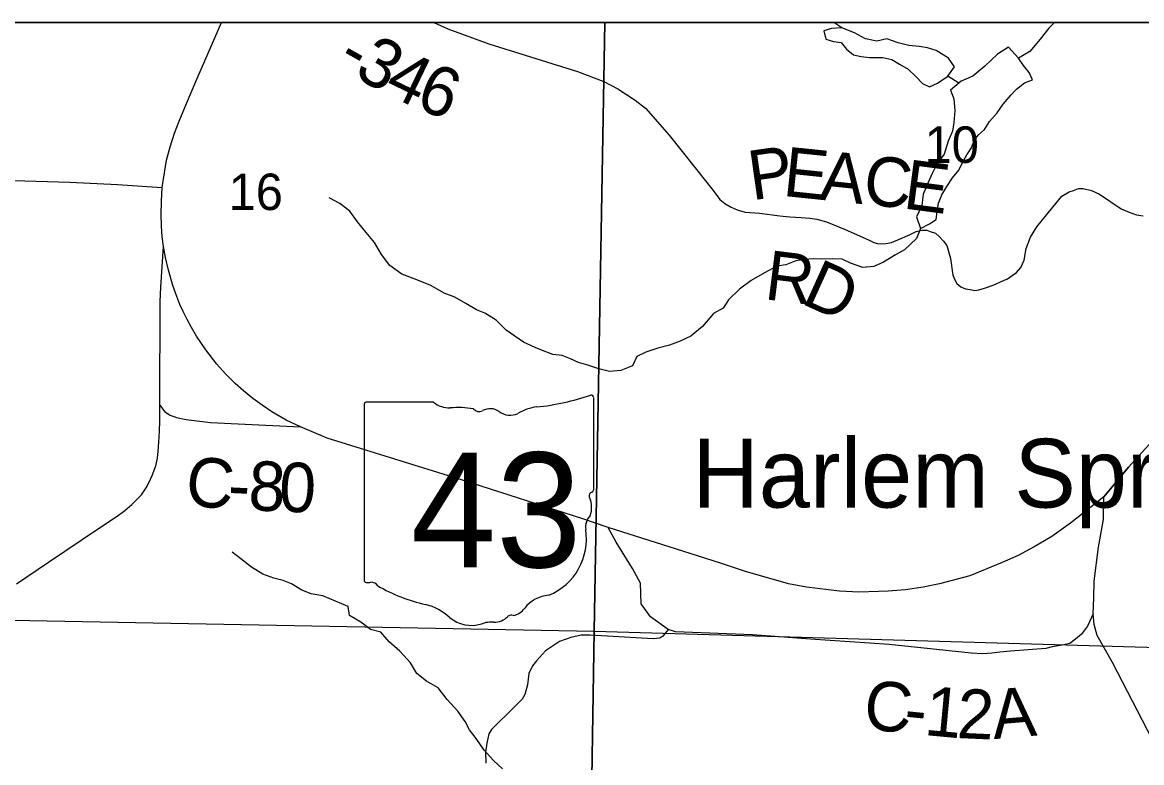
# Model space of a CAD drawing. Extents: x -3.6 to 34, y 0 to 32.8.
# Drawn here: x -2.413 to -1.128, y 31.993 to 32.843 of the extents above; entities that cross this region are included whole.
import ezdxf

# ---------------------------------------------------------------- set-up
doc = ezdxf.new("R2010")
doc.units = 0
for name, color, linetype in [('GM_X_Corporation', 7, 'Continuous'), ('GM_X_County_Road', 7, 'Continuous'), ('GM_X_County_Road_Text', 7, 'Continuous'), ('GM_X_Minor_Lake', 7, 'Continuous'), ('GM_X_Minor_River', 7, 'Continuous'), ('GM_X_Section_Text', 7, 'Continuous'), ('GM_X_State_Location', 7, 'Continuous'), ('GM_X_State_Route', 7, 'Continuous'), ('GM_X_State_Shield', 7, 'Continuous'), ('GM_X_Township_Road', 7, 'Continuous'), ('GM_X_Township_Road_Text', 7, 'Continuous'), ('GM_X_Unincorporated_Text', 7, 'Continuous'), ('SH_Data', 7, 'Continuous')]:
    doc.layers.add(name, color=color, linetype=linetype)

msp = doc.modelspace()

# ---------------------------------------------------------------- linework, layer by layer
at = {"layer": 'GM_X_Corporation'}
for points in [[(3.1705, 28.9337), (3.1705, 32.8429), (-3.6295, 32.8429), (-3.6295, 26.0429), (2.3706, 26.0429), (2.3712, 26.0804), (2.3716, 26.1248), (2.3732, 26.2253), (2.3789, 26.6097), (2.3911, 27.5117), (2.3952, 27.9336), (2.3997, 28.282), (2.4082, 28.9473), (2.5416, 28.945), (2.5837, 28.9442), (2.8343, 28.9397)], [(3.1705, 30.458), (3.1705, 32.8429), (-3.6295, 32.8429), (-3.6295, 30.6462), (-3.5736, 30.6453), (-2.8007, 30.6338), (-2.7027, 30.634), (-2.3541, 30.6318), (-0.5034, 30.5954), (-0.453, 30.5952), (-0.398, 30.5946), (0.2583, 30.5905), (0.2578, 30.5133), (0.3556, 30.5115), (0.4055, 30.5105), (1.2437, 30.4948), (1.7819, 30.4857), (3.0419, 30.4594)], [(-1.7439, 32.8429), (-2.7551, 32.8429), (-2.7692, 32.1629), (-1.7561, 32.1438)], [(-0.7278, 32.8429), (-1.7439, 32.8429), (-1.7561, 32.1438), (-0.7385, 32.1141)], [(-2.7692, 32.1629), (-1.7561, 32.1438), (-1.7722, 31.1326), (-2.786, 31.1483)], [(-1.7561, 32.1438), (-0.7385, 32.1141), (-0.7569, 31.1125), (-1.7722, 31.1326)]]:
    msp.add_lwpolyline(points, close=True, dxfattribs=at)
at = {"layer": 'GM_X_County_Road'}
msp.add_line((-1.1709, 32.298), (-1.1593, 32.3119), dxfattribs=at)
for points in [[(-2.4353, 32.6616), (-2.3583, 32.6594), (-2.3035, 32.6568), (-2.2523, 32.6534)], [(-1.1593, 32.3119), (-1.1425, 32.3319), (-1.0919, 32.388), (-1.0547, 32.4298), (-1.0295, 32.4572)], [(-2.2549, 32.4034), (-2.2489, 32.3954), (-2.2431, 32.3919), (-2.2358, 32.389), (-2.2246, 32.3867), (-2.1966, 32.3833), (-2.0933, 32.3782)], [(-1.1094, 32.0076), (-1.1609, 32.1076), (-1.1787, 32.1385), (-1.1819, 32.1513), (-1.1831, 32.1635), (-1.1825, 32.1816), (-1.1819, 32.2012), (-1.177, 32.2402), (-1.1714, 32.2719), (-1.1713, 32.2845), (-1.1709, 32.298)], [(-1.1831, 32.1635), (-1.1898, 32.1494), (-1.1966, 32.1401), (-1.2036, 32.1343), (-1.2101, 32.1296), (-1.2188, 32.1277), (-1.2302, 32.1258), (-1.2376, 32.1239), (-1.2782, 32.1207), (-1.2904, 32.1194), (-1.2995, 32.1182), (-1.3097, 32.1178), (-1.3234, 32.1183), (-1.4174, 32.1285), (-1.5076, 32.1346), (-1.5742, 32.1394), (-1.6628, 32.1429), (-1.6712, 32.1454), (-1.6915, 32.16), (-1.7023, 32.175), (-1.703, 32.1988), (-1.7122, 32.2155), (-1.7307, 32.246), (-1.74, 32.2629)]]:
    msp.add_lwpolyline(points, dxfattribs=at)
at = {"layer": 'GM_X_Minor_Lake'}
for points in [[(-1.4717, 32.8367), (-1.4838, 32.8357), (-1.4925, 32.833), (-1.4901, 32.8235), (-1.4814, 32.821), (-1.4727, 32.8199), (-1.4665, 32.812), (-1.4585, 32.8057), (-1.4497, 32.8035), (-1.4399, 32.8025), (-1.4248, 32.8027), (-1.4145, 32.8001), (-1.4054, 32.7949), (-1.3955, 32.7893), (-1.387, 32.7807), (-1.379, 32.7728), (-1.371, 32.7688), (-1.362, 32.773), (-1.3501, 32.7809)], [(-1.3501, 32.7809), (-1.3424, 32.7919), (-1.3494, 32.8016), (-1.3635, 32.8105), (-1.3734, 32.8138), (-1.3828, 32.8152), (-1.395, 32.8162), (-1.4071, 32.8194), (-1.42, 32.8238), (-1.4314, 32.8214), (-1.4446, 32.8238), (-1.4572, 32.8309), (-1.4717, 32.8367)], [(-1.2689, 32.8018), (-1.2803, 32.8144), (-1.2931, 32.8062), (-1.3076, 32.7927), (-1.3214, 32.7812), (-1.3346, 32.7753), (-1.3469, 32.7649), (-1.343, 32.7551), (-1.342, 32.7418), (-1.3433, 32.7278), (-1.3447, 32.7179), (-1.3495, 32.7064), (-1.3542, 32.6916), (-1.3627, 32.6801), (-1.3678, 32.6702), (-1.373, 32.6583), (-1.3785, 32.6457), (-1.3801, 32.6324), (-1.386, 32.6195), (-1.3813, 32.6063)], [(-1.3813, 32.6063), (-1.371, 32.6114), (-1.3635, 32.6164), (-1.3624, 32.6251), (-1.3607, 32.6354), (-1.357, 32.6449), (-1.3511, 32.6545), (-1.3447, 32.6644), (-1.3373, 32.6732), (-1.3336, 32.6812), (-1.3284, 32.6908), (-1.3228, 32.6988), (-1.3199, 32.7075), (-1.3147, 32.7137), (-1.308, 32.7198), (-1.3024, 32.729), (-1.2934, 32.7389), (-1.2867, 32.7489), (-1.2774, 32.7596), (-1.2711, 32.7661), (-1.2621, 32.7734), (-1.253, 32.777), (-1.2565, 32.7853), (-1.2631, 32.7935), (-1.2689, 32.8018)]]:
    msp.add_lwpolyline(points, dxfattribs=at)
at = {"layer": 'GM_X_Minor_River'}
for points in [[(-1.2277, 32.8429), (-1.2341, 32.8362), (-1.2441, 32.8236), (-1.256, 32.8094), (-1.2689, 32.8018), (-1.2803, 32.8144), (-1.2931, 32.8062), (-1.3076, 32.7927), (-1.3214, 32.7812), (-1.3346, 32.7753), (-1.3469, 32.7649), (-1.343, 32.7551), (-1.342, 32.7418), (-1.3433, 32.7278), (-1.3447, 32.7179), (-1.3495, 32.7064), (-1.3542, 32.6916), (-1.3627, 32.6801), (-1.3678, 32.6702), (-1.373, 32.6583), (-1.3785, 32.6457), (-1.3801, 32.6324), (-1.386, 32.6195), (-1.3813, 32.6063), (-1.386, 32.5948), (-1.3998, 32.5817), (-1.4103, 32.5759), (-1.4238, 32.5674), (-1.4351, 32.5623), (-1.4476, 32.5614), (-1.462, 32.5665), (-1.4715, 32.5709), (-1.4821, 32.5711), (-1.4946, 32.5709), (-1.5045, 32.5712), (-1.5147, 32.5707), (-1.5245, 32.569), (-1.5361, 32.5643), (-1.5463, 32.563), (-1.5606, 32.5552), (-1.576, 32.5463), (-1.5894, 32.5366), (-1.6018, 32.5243), (-1.608, 32.5147), (-1.6193, 32.5085), (-1.6319, 32.4936), (-1.645, 32.4824), (-1.6574, 32.4769), (-1.6698, 32.4722), (-1.683, 32.4686), (-1.697, 32.4642), (-1.7071, 32.4591), (-1.7122, 32.4484), (-1.7254, 32.443), (-1.7386, 32.442), (-1.7508, 32.4449)], [(-1.3373, 32.773), (-1.3501, 32.7809), (-1.3424, 32.7919), (-1.3494, 32.8016), (-1.3635, 32.8105), (-1.3734, 32.8138), (-1.3828, 32.8152), (-1.395, 32.8162), (-1.4071, 32.8194), (-1.42, 32.8238), (-1.4314, 32.8214), (-1.4446, 32.8238), (-1.4572, 32.8309), (-1.4717, 32.8367), (-1.4809, 32.8429)], [(-1.7508, 32.4449), (-1.7633, 32.4493), (-1.774, 32.4521), (-1.7835, 32.4566), (-1.793, 32.4602), (-1.8036, 32.4616), (-1.8135, 32.4652), (-1.8238, 32.4693), (-1.8371, 32.4755), (-1.8474, 32.4826), (-1.8573, 32.4893), (-1.8685, 32.5009), (-1.8815, 32.5087), (-1.8914, 32.5127), (-1.9036, 32.5201), (-1.9162, 32.5271), (-1.9283, 32.5319), (-1.9436, 32.5408), (-1.9577, 32.5463), (-1.9676, 32.5503), (-1.9771, 32.5536), (-1.9909, 32.5636), (-2.0005, 32.5764), (-2.0083, 32.59), (-2.0179, 32.6016), (-2.0279, 32.6136), (-2.0368, 32.626), (-2.0483, 32.6349), (-2.0605, 32.6412)], [(-1.8613, 31.9856), (-1.8716, 31.9953), (-1.8824, 32.0069), (-1.8917, 32.0204), (-1.8994, 32.0302), (-1.9044, 32.04), (-1.9125, 32.0516), (-1.9249, 32.0651), (-1.9353, 32.0786), (-1.9486, 32.0864), (-1.9597, 32.095), (-1.9671, 32.1074), (-1.9794, 32.1205), (-1.9917, 32.1313), (-2.0009, 32.1426), (-2.013, 32.1454), (-2.0241, 32.154), (-2.0371, 32.1618), (-2.0384, 32.172), (-2.0677, 32.1841), (-2.081, 32.1866), (-2.0916, 32.1906), (-2.1035, 32.198), (-2.1134, 32.2017), (-2.124, 32.2046), (-2.1366, 32.2093), (-2.1495, 32.2171), (-2.1618, 32.2268), (-2.1717, 32.2342)]]:
    msp.add_lwpolyline(points, dxfattribs=at)
at = {"layer": 'GM_X_State_Route'}
msp.add_line((-1.1593, 32.3119), (-1.1709, 32.298), dxfattribs=at)
for points in [[(-2.2523, 32.6534), (-2.2496, 32.6699), (-2.247, 32.6847), (-2.2431, 32.7001), (-2.2381, 32.7155), (-2.2325, 32.7293), (-2.2243, 32.7495), (-2.2135, 32.7749), (-2.1994, 32.8076), (-2.1842, 32.8429)], [(-2.2508, 32.5855), (-2.2522, 32.5967), (-2.2528, 32.6091), (-2.2533, 32.6217), (-2.2531, 32.6374), (-2.2523, 32.6534)], [(-2.4194, 32.1979), (-2.3828, 32.2229), (-2.3254, 32.2614), (-2.3038, 32.2759), (-2.295, 32.2823), (-2.2869, 32.289), (-2.2759, 32.3004), (-2.2707, 32.3084), (-2.267, 32.3149), (-2.2635, 32.3224), (-2.2594, 32.3335), (-2.2576, 32.3425), (-2.2569, 32.3502), (-2.2561, 32.3607), (-2.2553, 32.3729), (-2.2549, 32.3857), (-2.2549, 32.4034), (-2.2543, 32.5221), (-2.2536, 32.5388), (-2.2508, 32.5855)], [(-1.1709, 32.298), (-1.2094, 32.2676), (-1.2307, 32.2525), (-1.2391, 32.2474), (-1.251, 32.2407), (-1.2695, 32.2307), (-1.2877, 32.2227), (-1.3247, 32.2073), (-1.3597, 32.1981), (-1.3785, 32.1943), (-1.3985, 32.1913), (-1.4187, 32.1896), (-1.4297, 32.1891), (-1.4521, 32.1885), (-1.4746, 32.1897), (-1.5122, 32.1941), (-1.533, 32.1982), (-1.5823, 32.2123), (-1.611, 32.2217), (-1.6616, 32.2379), (-1.74, 32.2629), (-1.769, 32.2725), (-1.9075, 32.3169), (-2.0628, 32.3655), (-2.0933, 32.3782), (-2.1097, 32.3861), (-2.1262, 32.3957), (-2.1374, 32.4031), (-2.1479, 32.4107), (-2.1588, 32.4195), (-2.1683, 32.4281), (-2.1794, 32.4393), (-2.1894, 32.4505), (-2.2021, 32.4668), (-2.2127, 32.4825), (-2.2186, 32.4925), (-2.2235, 32.5016), (-2.2282, 32.5109), (-2.2317, 32.519), (-2.2365, 32.531), (-2.2399, 32.5407), (-2.245, 32.5583), (-2.2485, 32.5727), (-2.2508, 32.5855)], [(-1.0295, 32.4572), (-1.0547, 32.4298), (-1.0919, 32.388), (-1.1425, 32.3319), (-1.1593, 32.3119)]]:
    msp.add_lwpolyline(points, dxfattribs=at)
at = {"layer": 'GM_X_State_Shield'}
for p, q in [((-1.7567, 32.3068), (-1.7567, 32.4114)), ((-2.0203, 32.403), (-2.0203, 32.2029)), ((-1.9405, 32.4065), (-2.0178, 32.4065)), ((-1.7567, 32.3068), (-1.7567, 32.3068))]:
    msp.add_line(p, q, dxfattribs=at)
for centre, radius, start, end in [((-1.8506, 32.6793), 0.2796, 275.8445, 288.9065), ((-1.7596, 32.4119), 0.00294, 351.8621, 97.738), ((-2.0173, 32.4035), 0.00305, 98.1301, 188.1301), ((-1.9221, 32.4297), 0.0296, 231.6195, 271.1119), ((-1.9123, 32.2941), 0.1064, 80.4867, 94.9883), ((-1.8882, 32.4045), 0.00855, 219.7921, 297.1024), ((-1.8756, 32.3814), 0.0178, 54.4667, 119.1411), ((-1.8149, 32.3454), 0.0563, 97.3462, 120.7689), ((-1.8527, 32.4131), 0.0214, 233.8562, 294.8282), ((-1.7598, 32.3064), 0.00314, 289.6038, 7.7341), ((-1.7574, 32.2991), 0.00454, 107.944, 210.337), ((-1.7863, 32.2858), 0.0273, 340.033, 23.6496), ((-1.7462, 32.263), 0.0198, 136.8065, 186.9296), ((-1.8349, 32.2496), 0.0699, 292.3089, 8.9858), ((-2.0173, 32.2025), 0.00308, 171.9584, 258.3066), ((-2.0168, 32.223), 0.0235, 267.339, 280.6039), ((-2.012, 32.1914), 0.00848, 29.7484, 93.2717), ((-1.905, 32.3712), 0.2019, 240.4129, 257.1985), ((-1.8055, 32.1467), 0.0383, 94.4031, 142.5768), ((-1.9652, 32.113), 0.0632, 47.1842, 75.836), ((-1.854, 32.1835), 0.0226, 282.8732, 323.2771), ((-1.8968, 32.1904), 0.0401, 230.7004, 286.2918), ((-1.8737, 32.1212), 0.0329, 85.6951, 111.2099), ((-1.8707, 32.1754), 0.0214, 268.777, 315.5493), ((-1.8514, 32.156), 0.00601, 65.7517, 132.6484)]:
    msp.add_arc(centre, radius, start, end, dxfattribs=at)
at = {"layer": 'GM_X_Township_Road'}
for points in [[(-1.9401, 32.8429), (-1.9242, 32.8353), (-1.8771, 32.8184), (-1.7754, 32.7866), (-1.7451, 32.7749), (-1.7288, 32.7665), (-1.7091, 32.7536), (-1.6972, 32.7444), (-1.6701, 32.7133), (-1.6269, 32.6591), (-1.6184, 32.6483), (-1.6118, 32.6393), (-1.6061, 32.6347), (-1.5988, 32.6306), (-1.592, 32.6274), (-1.5829, 32.6248), (-1.5664, 32.6236), (-1.5431, 32.6208), (-1.5315, 32.6196), (-1.5185, 32.6187), (-1.5087, 32.618), (-1.5006, 32.6167), (-1.4895, 32.6136), (-1.4681, 32.6051), (-1.4412, 32.5931), (-1.4352, 32.5902), (-1.4308, 32.5888), (-1.4267, 32.5885), (-1.4212, 32.589), (-1.4149, 32.59), (-1.4047, 32.5944), (-1.3932, 32.5992), (-1.3865, 32.6027), (-1.3799, 32.6043), (-1.3741, 32.6041), (-1.3702, 32.6027), (-1.3643, 32.6008), (-1.36, 32.5968), (-1.3549, 32.5917), (-1.3513, 32.5866), (-1.3469, 32.5716), (-1.3445, 32.5525), (-1.3421, 32.5473), (-1.3396, 32.5429), (-1.3352, 32.539), (-1.3298, 32.537), (-1.3243, 32.5359), (-1.3192, 32.535), (-1.3146, 32.5357), (-1.3081, 32.5376), (-1.2982, 32.5411), (-1.2863, 32.5465), (-1.2816, 32.5485), (-1.2761, 32.552), (-1.2712, 32.5554), (-1.2664, 32.5612), (-1.2623, 32.5699), (-1.2603, 32.5831), (-1.255, 32.5963), (-1.2477, 32.608), (-1.2415, 32.6162), (-1.2193, 32.6434), (-1.2109, 32.6482), (-1.2057, 32.6499), (-1.2002, 32.6519), (-1.1947, 32.6522), (-1.1851, 32.6498), (-1.1759, 32.6454), (-1.1511, 32.6289), (-1.1419, 32.6247), (-1.1336, 32.622), (-1.1259, 32.6206)], [(-1.6712, 32.1454), (-1.6772, 32.1378), (-1.6809, 32.1358), (-1.6885, 32.1349), (-1.7606, 32.1391), (-1.771, 32.1392), (-1.7828, 32.1364), (-1.796, 32.1317), (-1.8119, 32.1209), (-1.8224, 32.1097), (-1.8271, 32.1037), (-1.8313, 32.0952), (-1.8327, 32.0822), (-1.8359, 32.0711), (-1.8389, 32.0654), (-1.8472, 32.057), (-1.8739, 32.0306), (-1.8772, 32.0258), (-1.8794, 32.0152), (-1.8808, 32.0045), (-1.8806, 31.992)]]:
    msp.add_lwpolyline(points, dxfattribs=at)
at = {"layer": 'SH_Data'}
msp.add_line((-3.6295, 32.8429), (3.1705, 32.8429), dxfattribs=at)

# ---------------------------------------------------------------- texts
at = {"layer": 'GM_X_County_Road_Text'}
for s, rotation, p in [('C', 354.6137, (-2.2268, 32.2884)), ('8', 357.5964, (-2.1539, 32.2827)), ('0', 357.7127, (-2.1188, 32.2812)), ('-', 357.3117, (-2.1775, 32.2838)), ('C', 354.2156, (-1.4483, 32.0316)), ('1', 354.6332, (-1.3782, 32.0245)), ('2', 357.3947, (-1.3404, 32.021)), ('A', 4.8796, (-1.2973, 32.0196)), ('-', 354.295, (-1.4018, 32.0269))]:
    msp.add_text(s, height=0.0568, rotation=rotation, dxfattribs=at).set_placement(p)
at = {"layer": 'GM_X_Section_Text'}
for s, p in [('10', (-1.3767, 32.6815)), ('16', (-2.1758, 32.6273))]:
    msp.add_text(s, height=0.04186, rotation=0, dxfattribs=at).set_placement(p)
at = {"layer": 'GM_X_State_Location'}
for s in ['s', 'r']:
    msp.add_text(s, height=0.000189, dxfattribs=at).set_placement((-1.8915, 32.2897))
msp.add_text('43', height=0.000189, rotation=0, dxfattribs=at).set_placement((-1.9392, 32.2759))
at = {"layer": 'GM_X_State_Shield'}
msp.add_text('43', height=0.13184, dxfattribs=at).set_placement((-1.9667, 32.217))
at = {"layer": 'GM_X_Township_Road_Text'}
for s, rotation, p in [('3', 330.5036, (-2.0334, 32.7816)), ('-', 330.5383, (-2.0537, 32.7931)), ('4', 334.2842, (-1.9993, 32.7625)), ('6', 338.8826, (-1.9632, 32.7453)), ('P', 8.0733, (-1.5749, 32.6384)), ('E', 354.0881, (-1.5406, 32.6437)), ('A', 354.0697, (-1.4984, 32.6393)), ('C', 354.0529, (-1.4486, 32.6342)), ('E', 352.4529, (-1.4026, 32.6294)), ('R', 352.8232, (-1.5618, 32.5251)), ('D', 335.6625, (-1.5198, 32.5205))]:
    msp.add_text(s, height=0.0568, rotation=rotation, dxfattribs=at).set_placement(p)
at = {"layer": 'GM_X_Unincorporated_Text'}
msp.add_text('Harlem Springs', height=0.078977, rotation=0, dxfattribs=at).set_placement((-1.6433, 32.2856))

doc.saveas('drawing.dxf')
